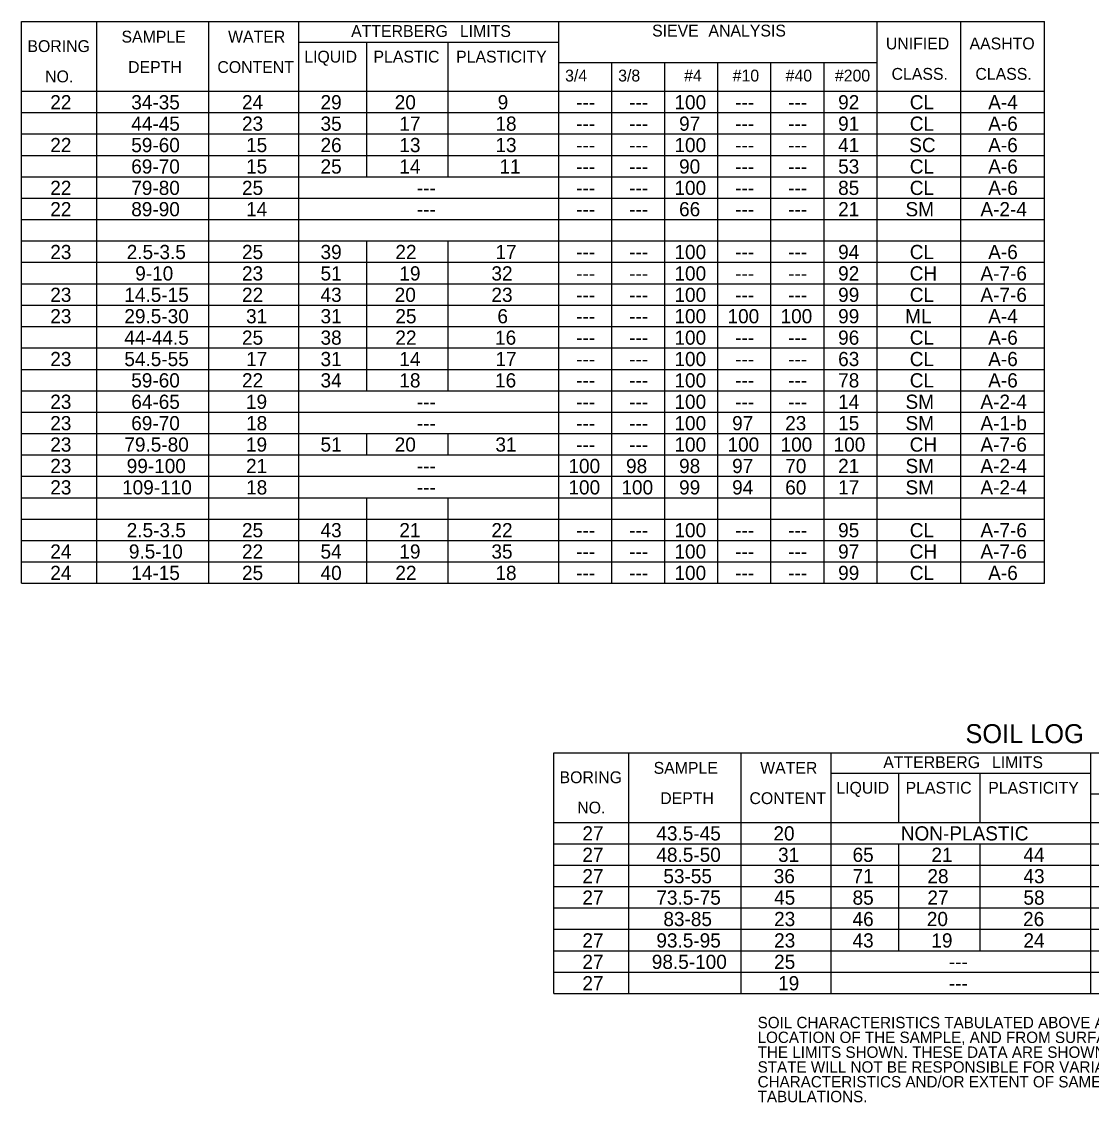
# Model space of a CAD drawing. Extents: x 1197542 to 1207464, y 185022 to 237324.
# Drawn here: x 1207185.3 to 1207298.3, y 185026.2 to 185140.3 of the extents above; entities that cross this region are included whole.
import ezdxf

# ---------------------------------------------------------------- set-up
doc = ezdxf.new("R2010")
doc.units = 0
doc.layers.add('R_No Plot', color=7, linetype='Continuous')

msp = doc.modelspace()

# ---------------------------------------------------------------- linework, layer by layer
at = {"layer": 'R_No Plot'}
for p, q in [((1207185.34, 185140.29), (1207185.34, 185140.29)), ((1207185.34, 185140.29), (1207293.3, 185140.29)), ((1207185.34, 185081), (1207185.34, 185140.29)), ((1207193.27, 185081), (1207193.27, 185140.29)), ((1207205.11, 185081), (1207205.11, 185140.29)), ((1207214.61, 185081), (1207214.61, 185140.29)), ((1207242.05, 185081), (1207242.05, 185140.29)), ((1207275.64, 185081), (1207275.64, 185140.29)), ((1207284.47, 185081), (1207284.47, 185140.29)), ((1207293.3, 185081), (1207293.3, 185140.29)), ((1207214.61, 185138.13), (1207242.05, 185138.13)), ((1207221.77, 185123.91), (1207221.77, 185138.13)), ((1207230.35, 185123.91), (1207230.35, 185138.13)), ((1207242.05, 185135.97), (1207275.64, 185135.97)), ((1207247.65, 185081), (1207247.65, 185135.97)), ((1207253.25, 185081), (1207253.25, 185135.97)), ((1207258.84, 185081), (1207258.84, 185135.97)), ((1207264.44, 185081), (1207264.44, 185135.97)), ((1207270.04, 185081), (1207270.04, 185135.97)), ((1207185.34, 185132.95), (1207293.3, 185132.95)), ((1207275.64, 185132.95), (1207293.3, 185132.95)), ((1207185.34, 185130.69), (1207293.3, 185130.69)), ((1207185.34, 185128.43), (1207293.3, 185128.43)), ((1207185.34, 185126.17), (1207293.3, 185126.17)), ((1207185.34, 185123.91), (1207293.3, 185123.91)), ((1207185.34, 185121.65), (1207293.3, 185121.65)), ((1207185.34, 185119.39), (1207293.3, 185119.39)), ((1207185.34, 185117.14), (1207293.3, 185117.14)), ((1207221.77, 185101.32), (1207221.77, 185117.14)), ((1207230.35, 185101.32), (1207230.35, 185117.14)), ((1207185.34, 185114.88), (1207293.3, 185114.88)), ((1207185.34, 185112.62), (1207293.3, 185112.62)), ((1207185.34, 185110.36), (1207293.3, 185110.36)), ((1207185.34, 185108.1), (1207293.3, 185108.1)), ((1207185.34, 185105.84), (1207293.3, 185105.84)), ((1207185.34, 185103.58), (1207293.3, 185103.58)), ((1207185.34, 185101.32), (1207293.3, 185101.32)), ((1207185.34, 185099.07), (1207293.3, 185099.07)), ((1207185.34, 185096.81), (1207293.3, 185096.81)), ((1207221.77, 185094.55), (1207221.77, 185096.81)), ((1207230.35, 185094.55), (1207230.35, 185096.81)), ((1207185.34, 185094.55), (1207293.3, 185094.55)), ((1207185.34, 185092.29), (1207293.3, 185092.29)), ((1207185.34, 185090.03), (1207293.3, 185090.03)), ((1207221.77, 185081), (1207221.77, 185090.03)), ((1207230.35, 185081), (1207230.35, 185090.03)), ((1207185.34, 185087.77), (1207293.3, 185087.77)), ((1207185.34, 185085.51), (1207293.3, 185085.51)), ((1207185.34, 185083.25), (1207293.3, 185083.25)), ((1207185.34, 185081), (1207293.3, 185081)), ((1207241.5, 185063.1), (1207241.5, 185063.1)), ((1207241.5, 185063.1), (1207349.47, 185063.1)), ((1207241.5, 185037.68), (1207241.5, 185063.1)), ((1207249.44, 185037.68), (1207249.44, 185063.1)), ((1207261.28, 185037.68), (1207261.28, 185063.1)), ((1207270.78, 185037.68), (1207270.78, 185063.1)), ((1207298.22, 185037.68), (1207298.22, 185063.1)), ((1207270.78, 185060.94), (1207298.22, 185060.94)), ((1207277.94, 185055.75), (1207277.94, 185060.94)), ((1207286.52, 185055.75), (1207286.52, 185060.94)), ((1207298.22, 185058.78), (1207331.81, 185058.78)), ((1207241.5, 185055.75), (1207349.47, 185055.75)), ((1207241.5, 185053.49), (1207349.47, 185053.49)), ((1207277.94, 185042.2), (1207277.94, 185053.49)), ((1207286.52, 185042.2), (1207286.52, 185053.49)), ((1207241.5, 185051.24), (1207349.47, 185051.24)), ((1207241.5, 185048.98), (1207349.47, 185048.98)), ((1207241.5, 185046.72), (1207349.47, 185046.72)), ((1207241.5, 185044.46), (1207349.47, 185044.46)), ((1207241.5, 185042.2), (1207349.47, 185042.2)), ((1207241.5, 185039.94), (1207349.47, 185039.94)), ((1207241.5, 185037.68), (1207349.47, 185037.68))]:
    msp.add_line(p, q, dxfattribs=at)

# ---------------------------------------------------------------- texts
for s, height, p in [('SAMPLE', 1.25, (1207195.88, 185138.08)), ('WATER', 1.25, (1207207.13, 185138.08)), ('ATTERBERG', 1.25, (1207220.12, 185138.67)), ('LIMITS', 1.25, (1207231.6, 185138.67)), ('SIEVE', 1.25, (1207251.89, 185138.72)), ('ANALYSIS', 1.25, (1207257.84, 185138.72)), ('BORING', 1.25, (1207185.95, 185137.08)), ('UNIFIED', 1.25, (1207276.57, 185137.36)), ('AASHTO', 1.25, (1207285.4, 185137.36)), ('LIQUID', 1.25, (1207215.17, 185135.97)), ('PLASTIC', 1.25, (1207222.48, 185135.97)), ('PLASTICITY', 1.25, (1207231.2, 185135.97)), ('DEPTH', 1.25, (1207196.58, 185134.87)), ('CONTENT', 1.25, (1207206, 185134.87)), ('NO.', 1.25, (1207187.82, 185133.88)), ('3/4', 1.25, (1207242.71, 185133.97)), ('3/8', 1.25, (1207248.31, 185133.97)), ('#4', 1.25, (1207255.27, 185133.97)), ('#10', 1.25, (1207260.4, 185133.97)), ('#40', 1.25, (1207265.99, 185133.97)), ('#200', 1.25, (1207271.19, 185133.97)), ('CLASS.', 1.25, (1207277.17, 185134.15)), ('CLASS.', 1.25, (1207286.02, 185134.15)), ('22', 1.5, (1207188.36, 185131.03)), ('34-35', 1.5, (1207196.91, 185131.03)), ('24', 1.5, (1207208.6, 185131.03)), ('29', 1.5, (1207216.89, 185131.03)), ('20', 1.5, (1207224.72, 185131.03)), ('9', 1.5, (1207235.59, 185131.03)), ('100', 1.5, (1207254.25, 185131.03)), ('92', 1.5, (1207271.53, 185131.03)), ('CL', 1.5, (1207279.09, 185131.03)), ('A-4', 1.5, (1207287.37, 185131.03)), ('---', 1.5, (1207243.88, 185131.03)), ('---', 1.5, (1207249.48, 185131.03)), ('---', 1.5, (1207260.67, 185131.03)), ('---', 1.5, (1207266.27, 185131.03)), ('44-45', 1.5, (1207196.91, 185128.77)), ('23', 1.5, (1207208.6, 185128.77)), ('35', 1.5, (1207216.89, 185128.77)), ('17', 1.5, (1207225.21, 185128.77)), ('18', 1.5, (1207235.35, 185128.77)), ('97', 1.5, (1207254.74, 185128.77)), ('91', 1.5, (1207271.53, 185128.77)), ('CL', 1.5, (1207279.09, 185128.77)), ('A-6', 1.5, (1207287.37, 185128.77)), ('---', 1.5, (1207243.88, 185128.77)), ('---', 1.5, (1207249.48, 185128.77)), ('---', 1.5, (1207260.67, 185128.77)), ('---', 1.5, (1207266.27, 185128.77)), ('22', 1.5, (1207188.36, 185126.51)), ('59-60', 1.5, (1207196.91, 185126.51)), ('15', 1.5, (1207209.03, 185126.51)), ('26', 1.5, (1207216.89, 185126.51)), ('13', 1.5, (1207225.21, 185126.51)), ('13', 1.5, (1207235.35, 185126.51)), ('100', 1.5, (1207254.25, 185126.51)), ('41', 1.5, (1207271.53, 185126.51)), ('SC', 1.5, (1207279.03, 185126.51)), ('A-6', 1.5, (1207287.37, 185126.51)), ('---', 1.5, (1207243.88, 185126.51)), ('---', 1.5, (1207249.48, 185126.51)), ('---', 1.5, (1207260.67, 185126.51)), ('---', 1.5, (1207266.27, 185126.51)), ('69-70', 1.5, (1207196.91, 185124.25)), ('15', 1.5, (1207209.03, 185124.25)), ('25', 1.5, (1207216.89, 185124.25)), ('14', 1.5, (1207225.21, 185124.25)), ('11', 1.5, (1207235.78, 185124.25)), ('90', 1.5, (1207254.74, 185124.25)), ('53', 1.5, (1207271.53, 185124.25)), ('CL', 1.5, (1207279.09, 185124.25)), ('A-6', 1.5, (1207287.37, 185124.25)), ('---', 1.5, (1207243.88, 185124.25)), ('---', 1.5, (1207249.48, 185124.25)), ('---', 1.5, (1207260.67, 185124.25)), ('---', 1.5, (1207266.27, 185124.25)), ('22', 1.5, (1207188.36, 185121.99)), ('79-80', 1.5, (1207196.91, 185121.99)), ('25', 1.5, (1207208.6, 185121.99)), ('100', 1.5, (1207254.25, 185121.99)), ('85', 1.5, (1207271.53, 185121.99)), ('CL', 1.5, (1207279.09, 185121.99)), ('A-6', 1.5, (1207287.37, 185121.99)), ('---', 1.5, (1207227.05, 185122)), ('---', 1.5, (1207243.88, 185121.99)), ('---', 1.5, (1207249.48, 185121.99)), ('---', 1.5, (1207260.67, 185121.99)), ('---', 1.5, (1207266.27, 185121.99)), ('22', 1.5, (1207188.36, 185119.74)), ('89-90', 1.5, (1207196.91, 185119.74)), ('14', 1.5, (1207209.03, 185119.74)), ('66', 1.5, (1207254.74, 185119.74)), ('21', 1.5, (1207271.53, 185119.74)), ('SM', 1.5, (1207278.64, 185119.74)), ('A-2-4', 1.5, (1207286.55, 185119.74)), ('---', 1.5, (1207227.05, 185119.74)), ('---', 1.5, (1207243.88, 185119.74)), ('---', 1.5, (1207249.48, 185119.74)), ('---', 1.5, (1207260.67, 185119.74)), ('---', 1.5, (1207266.27, 185119.74)), ('23', 1.5, (1207188.36, 185115.22)), ('2.5-3.5', 1.5, (1207196.43, 185115.22)), ('25', 1.5, (1207208.6, 185115.22)), ('39', 1.5, (1207216.89, 185115.22)), ('22', 1.5, (1207224.79, 185115.22)), ('17', 1.5, (1207235.35, 185115.22)), ('100', 1.5, (1207254.25, 185115.22)), ('94', 1.5, (1207271.53, 185115.22)), ('CL', 1.5, (1207279.09, 185115.22)), ('A-6', 1.5, (1207287.37, 185115.22)), ('---', 1.5, (1207243.88, 185115.22)), ('---', 1.5, (1207249.48, 185115.22)), ('---', 1.5, (1207260.67, 185115.22)), ('---', 1.5, (1207266.27, 185115.22)), ('9-10', 1.5, (1207197.33, 185112.96)), ('23', 1.5, (1207208.6, 185112.96)), ('51', 1.5, (1207216.89, 185112.96)), ('19', 1.5, (1207225.21, 185112.96)), ('32', 1.5, (1207234.93, 185112.96)), ('100', 1.5, (1207254.25, 185112.96)), ('92', 1.5, (1207271.53, 185112.96)), ('CH', 1.5, (1207279.08, 185112.96)), ('A-7-6', 1.5, (1207286.55, 185112.96)), ('---', 1.5, (1207243.88, 185112.96)), ('---', 1.5, (1207249.48, 185112.96)), ('---', 1.5, (1207260.67, 185112.96)), ('---', 1.5, (1207266.27, 185112.96)), ('23', 1.5, (1207188.36, 185110.7)), ('14.5-15', 1.5, (1207196.18, 185110.7)), ('22', 1.5, (1207208.6, 185110.7)), ('43', 1.5, (1207216.89, 185110.7)), ('20', 1.5, (1207224.72, 185110.7)), ('23', 1.5, (1207234.93, 185110.7)), ('100', 1.5, (1207254.25, 185110.7)), ('99', 1.5, (1207271.53, 185110.7)), ('CL', 1.5, (1207279.09, 185110.7)), ('A-7-6', 1.5, (1207286.55, 185110.7)), ('---', 1.5, (1207243.88, 185110.7)), ('---', 1.5, (1207249.48, 185110.7)), ('---', 1.5, (1207260.67, 185110.7)), ('---', 1.5, (1207266.27, 185110.7)), ('23', 1.5, (1207188.36, 185108.44)), ('29.5-30', 1.5, (1207196.18, 185108.44)), ('31', 1.5, (1207209.03, 185108.44)), ('31', 1.5, (1207216.89, 185108.44)), ('25', 1.5, (1207224.79, 185108.44)), ('6', 1.5, (1207235.56, 185108.44)), ('100', 1.5, (1207254.25, 185108.44)), ('100', 1.5, (1207259.85, 185108.44)), ('100', 1.5, (1207265.45, 185108.44)), ('99', 1.5, (1207271.53, 185108.44)), ('ML', 1.5, (1207278.6, 185108.44)), ('A-4', 1.5, (1207287.37, 185108.44)), ('---', 1.5, (1207243.88, 185108.44)), ('---', 1.5, (1207249.48, 185108.44)), ('44-44.5', 1.5, (1207196.18, 185106.18)), ('25', 1.5, (1207208.6, 185106.18)), ('38', 1.5, (1207216.89, 185106.18)), ('22', 1.5, (1207224.79, 185106.18)), ('16', 1.5, (1207235.31, 185106.18)), ('100', 1.5, (1207254.25, 185106.18)), ('96', 1.5, (1207271.53, 185106.18)), ('CL', 1.5, (1207279.09, 185106.18)), ('A-6', 1.5, (1207287.37, 185106.18)), ('---', 1.5, (1207243.88, 185106.18)), ('---', 1.5, (1207249.48, 185106.18)), ('---', 1.5, (1207260.67, 185106.18)), ('---', 1.5, (1207266.27, 185106.18)), ('23', 1.5, (1207188.36, 185103.92)), ('54.5-55', 1.5, (1207196.18, 185103.92)), ('17', 1.5, (1207209.03, 185103.92)), ('31', 1.5, (1207216.89, 185103.92)), ('14', 1.5, (1207225.21, 185103.92)), ('17', 1.5, (1207235.35, 185103.92)), ('100', 1.5, (1207254.25, 185103.92)), ('63', 1.5, (1207271.53, 185103.92)), ('CL', 1.5, (1207279.09, 185103.92)), ('A-6', 1.5, (1207287.37, 185103.92)), ('---', 1.5, (1207243.88, 185103.92)), ('---', 1.5, (1207249.48, 185103.92)), ('---', 1.5, (1207260.67, 185103.92)), ('---', 1.5, (1207266.27, 185103.92)), ('59-60', 1.5, (1207196.91, 185101.67)), ('22', 1.5, (1207208.6, 185101.67)), ('34', 1.5, (1207216.89, 185101.67)), ('18', 1.5, (1207225.21, 185101.67)), ('16', 1.5, (1207235.31, 185101.67)), ('100', 1.5, (1207254.25, 185101.67)), ('78', 1.5, (1207271.53, 185101.67)), ('CL', 1.5, (1207279.09, 185101.67)), ('A-6', 1.5, (1207287.37, 185101.67)), ('---', 1.5, (1207243.88, 185101.67)), ('---', 1.5, (1207249.48, 185101.67)), ('---', 1.5, (1207260.67, 185101.67)), ('---', 1.5, (1207266.27, 185101.67)), ('23', 1.5, (1207188.36, 185099.41)), ('64-65', 1.5, (1207196.91, 185099.41)), ('19', 1.5, (1207209.02, 185099.41)), ('100', 1.5, (1207254.25, 185099.41)), ('14', 1.5, (1207271.53, 185099.41)), ('SM', 1.5, (1207278.64, 185099.41)), ('A-2-4', 1.5, (1207286.55, 185099.41)), ('---', 1.5, (1207227.05, 185099.41)), ('---', 1.5, (1207243.88, 185099.41)), ('---', 1.5, (1207249.48, 185099.41)), ('---', 1.5, (1207260.67, 185099.41)), ('---', 1.5, (1207266.27, 185099.41)), ('23', 1.5, (1207188.36, 185097.15)), ('69-70', 1.5, (1207196.91, 185097.15)), ('18', 1.5, (1207209.03, 185097.15)), ('100', 1.5, (1207254.25, 185097.15)), ('97', 1.5, (1207260.34, 185097.15)), ('23', 1.5, (1207265.94, 185097.15)), ('15', 1.5, (1207271.53, 185097.15)), ('SM', 1.5, (1207278.64, 185097.15)), ('A-1-b', 1.5, (1207286.55, 185097.15)), ('---', 1.5, (1207227.05, 185097.15)), ('---', 1.5, (1207243.88, 185097.15)), ('---', 1.5, (1207249.48, 185097.15)), ('23', 1.5, (1207188.36, 185094.89)), ('79.5-80', 1.5, (1207196.18, 185094.89)), ('19', 1.5, (1207209.02, 185094.89)), ('51', 1.5, (1207216.89, 185094.89)), ('20', 1.5, (1207224.72, 185094.89)), ('31', 1.5, (1207235.35, 185094.89)), ('100', 1.5, (1207254.25, 185094.89)), ('100', 1.5, (1207259.85, 185094.89)), ('100', 1.5, (1207265.45, 185094.89)), ('100', 1.5, (1207271.05, 185094.89)), ('CH', 1.5, (1207279.08, 185094.89)), ('A-7-6', 1.5, (1207286.55, 185094.89)), ('---', 1.5, (1207243.88, 185094.89)), ('---', 1.5, (1207249.48, 185094.89)), ('23', 1.5, (1207188.36, 185092.63)), ('99-100', 1.5, (1207196.43, 185092.63)), ('21', 1.5, (1207209.03, 185092.63)), ('---', 1.5, (1207227.05, 185092.63)), ('100', 1.5, (1207243.06, 185092.63)), ('98', 1.5, (1207249.14, 185092.63)), ('98', 1.5, (1207254.74, 185092.63)), ('97', 1.5, (1207260.34, 185092.63)), ('70', 1.5, (1207265.94, 185092.63)), ('21', 1.5, (1207271.53, 185092.63)), ('SM', 1.5, (1207278.64, 185092.63)), ('A-2-4', 1.5, (1207286.55, 185092.63)), ('23', 1.5, (1207188.36, 185090.37)), ('109-110', 1.5, (1207195.94, 185090.37)), ('18', 1.5, (1207209.03, 185090.37)), ('---', 1.5, (1207227.05, 185090.38)), ('100', 1.5, (1207243.06, 185090.37)), ('100', 1.5, (1207248.65, 185090.37)), ('99', 1.5, (1207254.74, 185090.37)), ('94', 1.5, (1207260.34, 185090.37)), ('60', 1.5, (1207265.94, 185090.37)), ('17', 1.5, (1207271.53, 185090.37)), ('SM', 1.5, (1207278.64, 185090.37)), ('A-2-4', 1.5, (1207286.55, 185090.37)), ('2.5-3.5', 1.5, (1207196.43, 185085.85)), ('25', 1.5, (1207208.6, 185085.85)), ('43', 1.5, (1207216.89, 185085.85)), ('21', 1.5, (1207225.21, 185085.85)), ('22', 1.5, (1207234.93, 185085.85)), ('---', 1.5, (1207243.88, 185085.85)), ('---', 1.5, (1207249.48, 185085.85)), ('100', 1.5, (1207254.25, 185085.85)), ('---', 1.5, (1207260.67, 185085.85)), ('---', 1.5, (1207266.27, 185085.85)), ('95', 1.5, (1207271.53, 185085.85)), ('CL', 1.5, (1207279.09, 185085.85)), ('A-7-6', 1.5, (1207286.55, 185085.85)), ('24', 1.5, (1207188.36, 185083.6)), ('9.5-10', 1.5, (1207196.66, 185083.6)), ('22', 1.5, (1207208.6, 185083.6)), ('54', 1.5, (1207216.89, 185083.6)), ('19', 1.5, (1207225.21, 185083.6)), ('35', 1.5, (1207234.93, 185083.6)), ('---', 1.5, (1207243.88, 185083.6)), ('---', 1.5, (1207249.48, 185083.6)), ('100', 1.5, (1207254.25, 185083.6)), ('---', 1.5, (1207260.67, 185083.6)), ('---', 1.5, (1207266.27, 185083.6)), ('97', 1.5, (1207271.53, 185083.6)), ('CH', 1.5, (1207279.08, 185083.6)), ('A-7-6', 1.5, (1207286.55, 185083.6)), ('24', 1.5, (1207188.36, 185081.34)), ('14-15', 1.5, (1207196.91, 185081.34)), ('25', 1.5, (1207208.6, 185081.34)), ('40', 1.5, (1207216.89, 185081.34)), ('22', 1.5, (1207224.79, 185081.34)), ('18', 1.5, (1207235.35, 185081.34)), ('---', 1.5, (1207243.88, 185081.34)), ('---', 1.5, (1207249.48, 185081.34)), ('100', 1.5, (1207254.25, 185081.34)), ('---', 1.5, (1207260.67, 185081.34)), ('---', 1.5, (1207266.27, 185081.34)), ('99', 1.5, (1207271.53, 185081.34)), ('CL', 1.5, (1207279.09, 185081.34)), ('A-6', 1.5, (1207287.37, 185081.34)), ('SOIL LOG', 2, (1207284.97, 185064.12)), ('ATTERBERG', 1.25, (1207276.29, 185061.48)), ('LIMITS', 1.25, (1207287.76, 185061.48)), ('SAMPLE', 1.25, (1207252.05, 185060.88)), ('WATER', 1.25, (1207263.3, 185060.88)), ('BORING', 1.25, (1207242.12, 185059.89)), ('LIQUID', 1.25, (1207271.34, 185058.78)), ('PLASTIC', 1.25, (1207278.65, 185058.78)), ('PLASTICITY', 1.25, (1207287.37, 185058.78)), ('NO.', 1.25, (1207243.99, 185056.69)), ('DEPTH', 1.25, (1207252.75, 185057.68)), ('CONTENT', 1.25, (1207262.17, 185057.68)), ('27', 1.5, (1207244.53, 185053.84)), ('43.5-45', 1.5, (1207252.34, 185053.84)), ('20', 1.5, (1207264.7, 185053.84)), ('NON-PLASTIC', 1.5, (1207278.14, 185053.84)), ('27', 1.5, (1207244.53, 185051.58)), ('48.5-50', 1.5, (1207252.34, 185051.58)), ('31', 1.5, (1207265.19, 185051.58)), ('65', 1.5, (1207273.05, 185051.58)), ('21', 1.5, (1207281.38, 185051.58)), ('44', 1.5, (1207291.09, 185051.58)), ('27', 1.5, (1207244.53, 185049.32)), ('53-55', 1.5, (1207253.08, 185049.32)), ('36', 1.5, (1207264.73, 185049.32)), ('71', 1.5, (1207273.05, 185049.32)), ('28', 1.5, (1207280.95, 185049.32)), ('43', 1.5, (1207291.09, 185049.32)), ('27', 1.5, (1207244.53, 185047.06)), ('73.5-75', 1.5, (1207252.34, 185047.06)), ('45', 1.5, (1207264.77, 185047.06)), ('85', 1.5, (1207273.05, 185047.06)), ('27', 1.5, (1207280.95, 185047.06)), ('58', 1.5, (1207291.09, 185047.06)), ('83-85', 1.5, (1207253.08, 185044.8)), ('23', 1.5, (1207264.77, 185044.8)), ('46', 1.5, (1207273.05, 185044.8)), ('20', 1.5, (1207280.89, 185044.8)), ('26', 1.5, (1207291.05, 185044.8)), ('27', 1.5, (1207244.53, 185042.54)), ('93.5-95', 1.5, (1207252.34, 185042.54)), ('23', 1.5, (1207264.77, 185042.54)), ('43', 1.5, (1207273.05, 185042.54)), ('19', 1.5, (1207281.37, 185042.54)), ('24', 1.5, (1207291.09, 185042.54)), ('27', 1.5, (1207244.53, 185040.28)), ('98.5-100', 1.5, (1207251.86, 185040.28)), ('25', 1.5, (1207264.77, 185040.28)), ('---', 1.5, (1207283.22, 185040.29)), ('27', 1.5, (1207244.53, 185038.02)), ('19', 1.5, (1207265.19, 185038.02)), ('---', 1.5, (1207283.22, 185038.03)), ('SOIL CHARACTERISTICS TABULATED ABOVE ARE REPRESENTATIVE AT THE ', 1.2, (1207263.03, 185034.02)), ('LOCATION OF THE SAMPLE, AND FROM SURFACE INDICATIONS ARE TYPICAL FOR ', 1.2, (1207263.03, 185032.46)), ('THE LIMITS SHOWN. THESE DATA ARE SHOWN FOR INFORMATION ONLY. THE ', 1.2, (1207263.03, 185030.89)), ('STATE WILL NOT BE RESPONSIBLE FOR VARIATIONS IN THE SOIL ', 1.2, (1207263.03, 185029.33)), ('CHARACTERISTICS AND/OR EXTENT OF SAME DIFFERING FROM THE ABOVE ', 1.2, (1207263.03, 185027.77)), ('TABULATIONS.', 1.2, (1207263.03, 185026.21))]:
    msp.add_text(s, height=height, dxfattribs=at).set_placement(p)

doc.saveas('drawing.dxf')
